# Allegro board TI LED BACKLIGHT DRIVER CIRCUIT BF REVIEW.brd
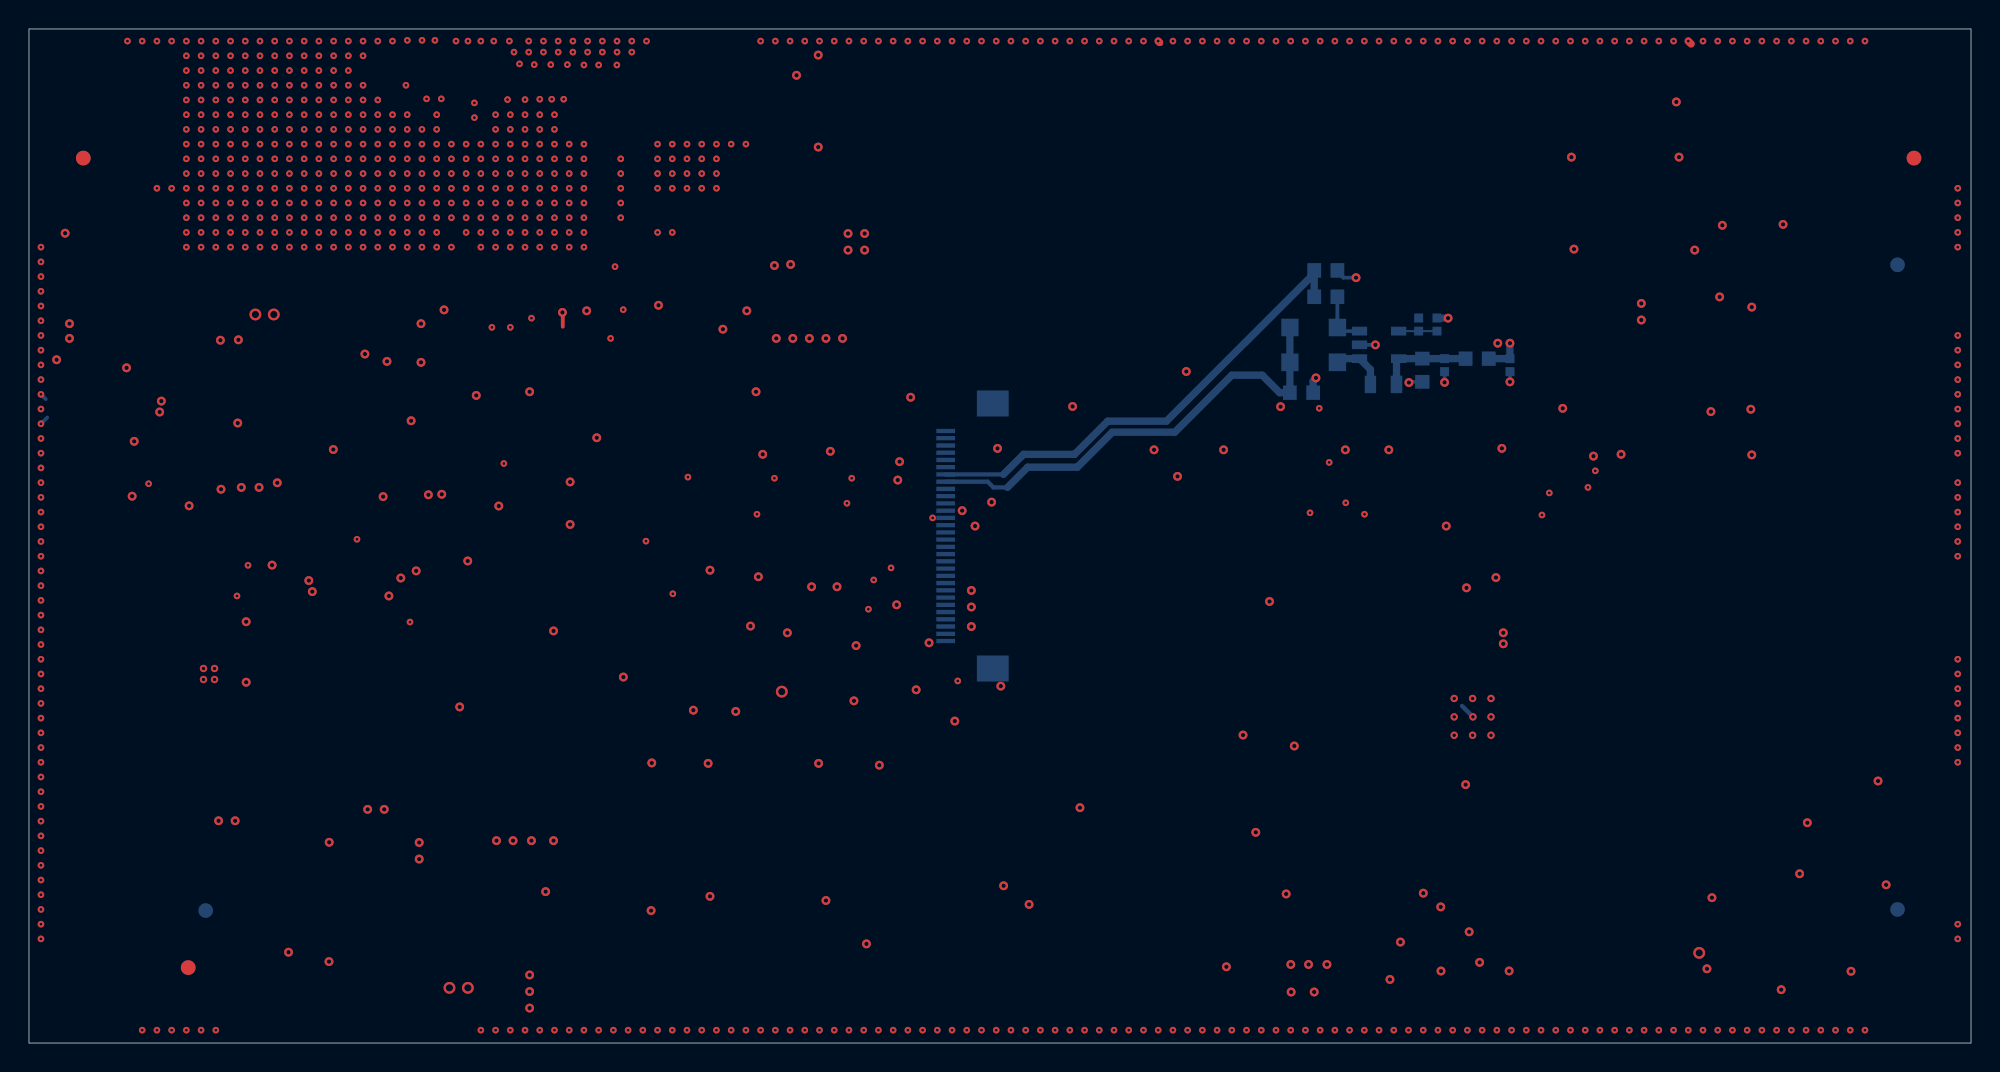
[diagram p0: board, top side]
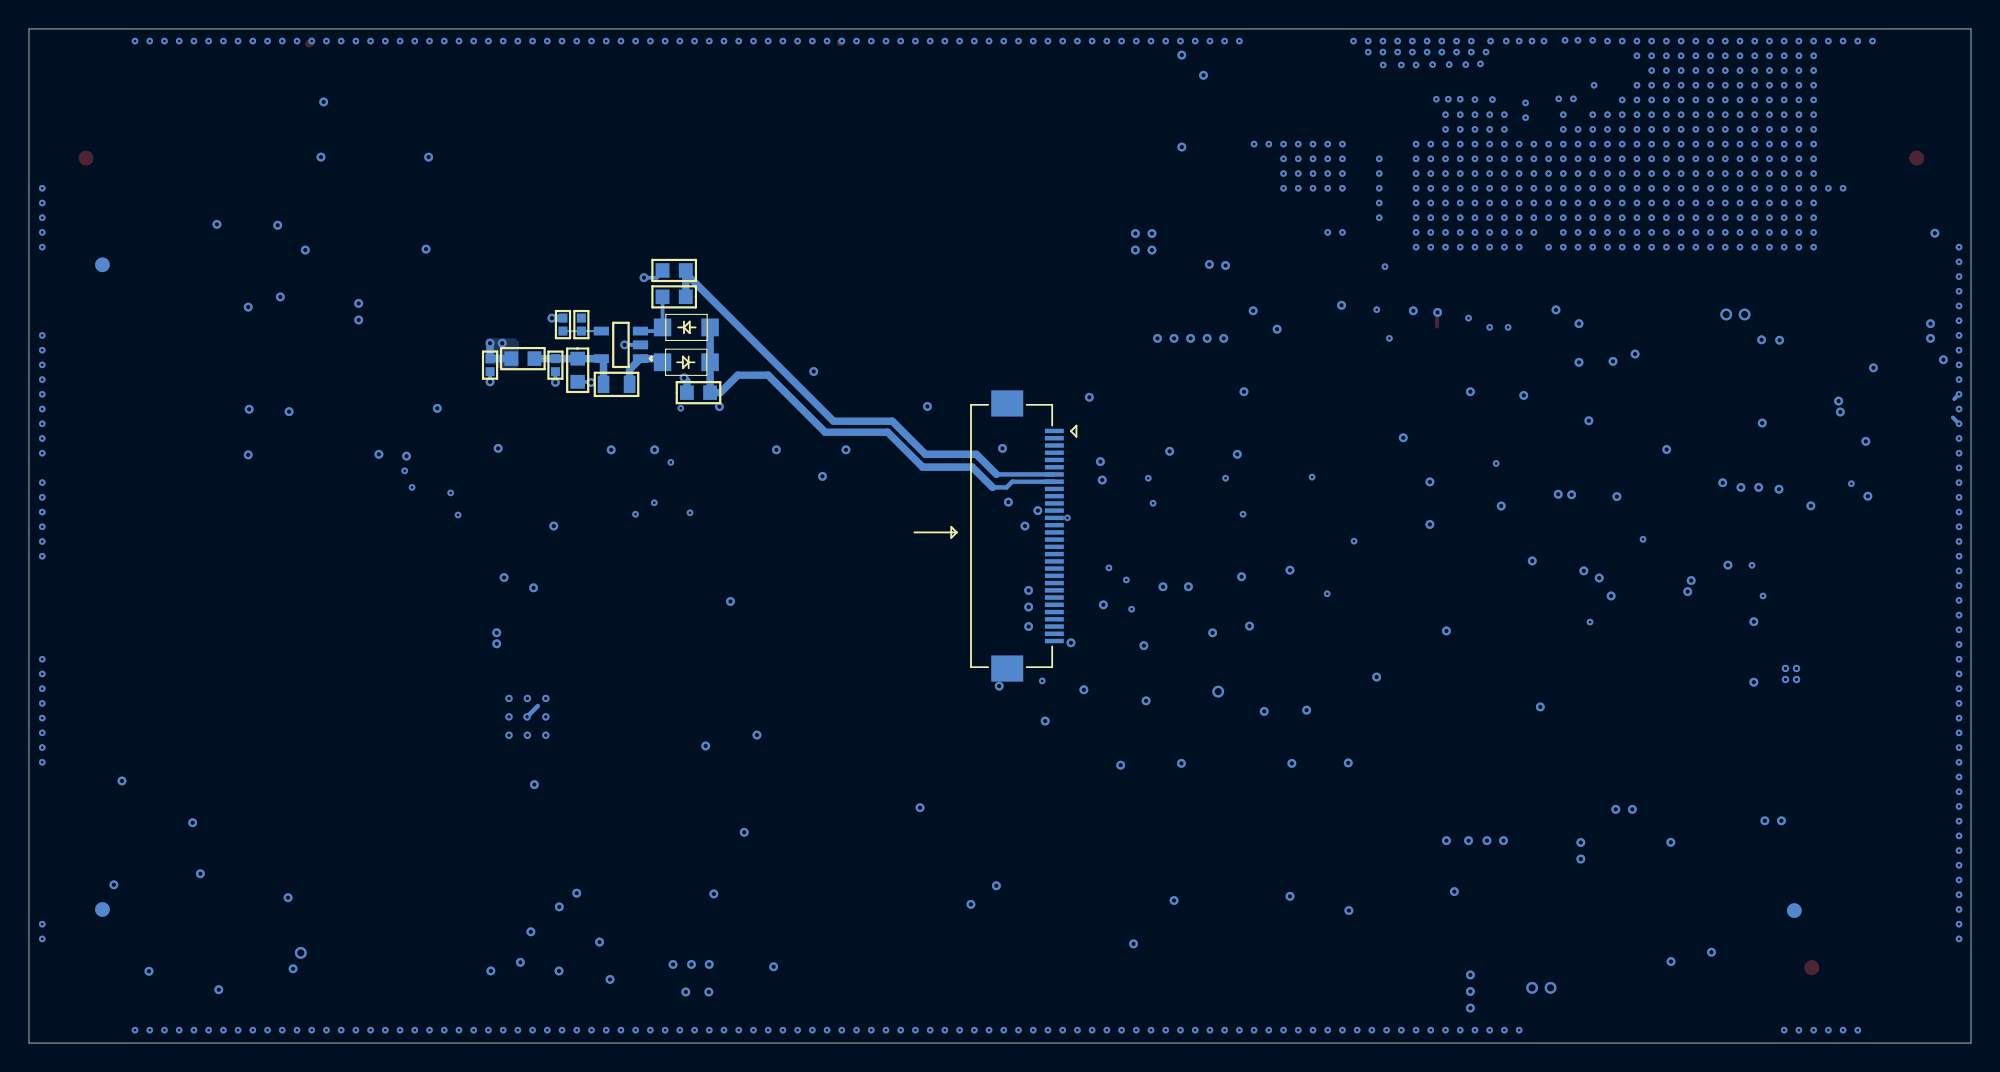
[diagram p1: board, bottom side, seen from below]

Outline 134 x 70 mm; copper layers: TOP, GND, SIG1, SIG2, VCC, BOTTOM. Coordinates in mm from the lower left corner of the outline.
Outline path: 0,70 0,0 134,0 134,70 0,70

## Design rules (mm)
net group DEFAULT: nets BACKLIGHT_DIM DIM_PWM1_OUT
net group POWER: nets GND LED_BACKLIGHT_A LED_BACKLIGHT_K N01711 N01793 VCC_3V3 VCC_5V_BCL VCC_5V_SW

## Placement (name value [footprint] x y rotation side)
C489  2.2uF,50V  [0603]  87.8 44.9 180 bottom
C490  10uF  [0603]  96.14 46.44 270 bottom
C491  0.1uF  [0402]  102.19 46.79 270 bottom
C749  0.1uF  [0402]  97.67 46.79 270 bottom
D51  PMEG4005EGWX  [SOD_123]  90.28 46.99 180 bottom
D52  DFLZ30-TP  [SOD_123]  87 49.4 0 bottom
FB66  74279228111  [0603]  99.92 47.24 0 bottom
J70  FH12S-30S-0-5SH_55  [HRS_FH12-30S-0_5SH]  63.25 42.25 270 bottom
L6  15uH  [IND_MLZ2012N]  94.36 45.47 180 bottom
NOREF  -  []  -123.96 2.55 90 top
NOREF#2  -  []  -32.31 7.14 90 top
NOREF#3  -  []  -30.16 5.64 90 top
NOREF#4  -  []  10.25 37.12 0 top
NOREF#5  -  []  -30.16 5.64 0 top
NOREF#6  -  []  10.6 41.2 0 top
NOREF#7  -  []  23.75 37.3 90 top
NOREF#8  -  []  4 0 90 top
NOREF#9  -  []  12.25 37.3 0 top
NOREF#10  -  []  -33.16 4.7 0 top
NOREF#11  -  []  -33.76 11.11 0 top
NOREF#12  -  []  -32.31 7.14 0 top
NOREF#13  -  []  -30.16 5.64 0 top
NOREF#14  -  []  -33.76 2.34 90 top
NOREF#15  -  []  -124.96 3.55 0 top
NOREF#16  -  []  17.75 37.3 0 top
NOREF#17  -  []  -124.71 3.47 0 top
NOREF#18  -  []  0 70 0 top
NOREF#19  -  []  -23.63 27.09 90 top
NOREF#20  -  []  -124.88 3.05 0 top
NOREF#21  -  []  -124.71 2.62 90 top
NOREF#22  -  []  -28.38 27.09 0 top
NOREF#23  -  []  -14.61 3.74 90 top
NOREF#24  -  []  299.21 -187.96 0 top
NOREF#25  -  []  -28.16 28.95 0 top
R611  0E  [0603]  89.48 51.51 0 bottom
R612  4.87E  [0603]  89.48 53.33 0 bottom
R613  0E  [0402]  95.88 49.59 90 bottom
R614  10K  [0402]  97.15 49.59 90 bottom
U27  LM3410XMF/NOPB  [SOT23X0_95X3_05X1_75X1_45-5]  91.81 47.24 90 bottom
UNK*  -  [unnamed#2]  3.75 61.09 0 top
UNK*#2  -  [unnamed#2]  10.99 5.21 0 top
UNK*#3  -  [unnamed#2]  130.07 61.09 0 top
UNK*#4  -  [unnamed#2]  12.19 9.14 180 bottom
UNK*#5  -  [unnamed#2]  128.93 9.22 180 bottom
UNK*#6  -  [unnamed#2]  128.93 53.72 180 bottom

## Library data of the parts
C489 = CAP NP
C490 C491 C749 = CAPACITOR NON-POL
D51 = DIODE SCHOTTKY
D52 = DIODE ZENER
FB66 = INDUCTOR FERRITE
J70 = FH12S-30S-0-5SH_3
L6 = INDUCTOR
R611-R614 = RES
U27 = LM3410XMF/NOPB

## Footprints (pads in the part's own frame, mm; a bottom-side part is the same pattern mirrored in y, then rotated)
0402
  rect 0.62x0.62 smd: 1(-0.45,0) 2(0.45,0)
0603
  rect 0.95x1 smd: 1(-0.8,0) 2(0.8,0)
HRS_FH12-30S-0_5SH
  rect 0.3x1.3 smd: 1(0,0) 2(0.5,0) 3(1,0) 4(1.5,0) 5(2,0) 6(2.5,0) 7(3,0) 8(3.5,0) 9(4,0) 10(4.5,0) 11(5,0) 12(5.5,0) 13(6,0) 14(6.5,0) 15(7,0) 16(7.5,0) 17(8,0) 18(8.5,0) 19(9,0) 20(9.5,0) 21(10,0) 22(10.5,0) 23(11,0) 24(11.5,0) 25(12,0) 26(12.5,0) 27(13,0) 28(13.5,0) 29(14,0) 30(14.5,0)
  rect 1.8x2.2 smd: MH1(16.4,-3.25) MH2(-1.9,-3.25)
IND_MLZ2012N
  rect 0.8x1.2 smd: 1(0,0) 2(1.8,0)
SOD_123
  rect 1.2x1.22 smd: 1(0,0) 2(3.28,0)
SOT23X0_95X3_05X1_75X1_45-5
  rect 0.6x1.05 smd: 1(0,0) 2(0.95,0) 3(1.9,0) 4(1.9,2.7) 5(0,2.7)
unnamed#2
  round 1.016 smd: (0,0)

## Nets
GND: C489.1 C490.2 C491.2 C749.2 R612.2 U27.2(GND)
GND1: J70.28(GND1)
GND2: J70.25(GND2)
GND4: J70.19(GND4)
GND5: J70.16(GND5)
GND6: J70.9(GND6)
VCC_3V3: R614.2
VCC_5V_BCL: C490.1 C749.1 FB66.1 L6.1 U27.5(VIN)
VCC_5V_SW: C491.1 FB66.2
BACKLIGHT_DIM: R613.1 R614.1 U27.4(DIM)
DIM_PWM1_OUT: R613.2
IOVCC: J70.15(IOVCC)
LED_BACKLIGHT_A: C489.2 D51.2(CATHODE) D52.1(CATHODE) J70.8(LEDA)
LED_BACKLIGHT_K: J70.7(LEDK) R611.1 R612.1
VCI: J70.10(VCI)
N01711: D51.1(ANODE) L6.2 U27.1(SW)
N01793: D52.2(ANODE) R611.2 U27.3(FB)

Pads without a net: J70 1 2 3 4 5 6 11 12 13 14 17 18 20 21 22 23 24 26 27 29 30 MH1 MH2

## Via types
v1: diameter 0.61, hole 0.305, TOP to BOTTOM, 188 vias
v2: diameter 0.813, hole 0.508, TOP to BOTTOM, 6 vias
v3: diameter 0.457, hole 0.203, TOP to BOTTOM, 700 vias
v4: diameter 0.508, hole 0.254, TOP to BOTTOM, 13 vias

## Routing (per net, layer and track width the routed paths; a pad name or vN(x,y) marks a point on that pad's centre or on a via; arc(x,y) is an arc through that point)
GND: length 10.1
  TOP w0.254: v1(36.81,50.43) 36.83,50.41 36.83,49.45 ; 78.11,68.97 78.01,69.07
  TOP w0.508: v3(114.49,69.16) 114.68,68.97 ; 78.01,69.07 v3(77.92,69.16)
  BOTTOM w0.144: 62.25,36.25 v3(62.35,36.25)
  BOTTOM w0.254: U27.2 v1(92.9,48.19) ; 1.16,44.45 v3(0.83,44.78) ; v1(91.57,52.83) 90.68,52.83 90.28,53.23 R612.2 ; 1.26,43.18 v3(0.83,42.75) ; C490.2 95.27,45.64 v1(95.21,45.59) ; C749.2 v1(97.67,45.6) ; v3(90.11,0.89) 90.1,0.89 ; 26.8,12.83 v1(26.92,12.7) ; C491.2 v1(102.19,45.64)
  BOTTOM w0.3: v4(99.63,22.52) 98.88,23.27
  BOTTOM w0.508: v1(88.8,45.92) 88.8,45.89 88.6,45.69 C489.1
  vias: v1(1.91,47.17) v1(2.49,55.9) v1(6.73,46.61) v1(7.12,37.75) v1(7.26,41.53) v1(9.02,43.56) v1(9.13,44.31) v1(11.05,37.08) v1(13.21,48.51) v1(13.25,38.23) v1(14.45,48.54) v1(14.4,42.8) v1(14.65,38.35) v1(14.99,29.08) v1(14.99,24.91) v1(15.88,38.35) v1(16.77,32.99) v1(17.13,38.68) v1(17.91,6.27) v1(19.31,31.92) v1(19.55,31.16) v1(20.71,13.86) v1(20.7,5.62) v1(21,40.97) v1(23.18,47.56) v1(23.37,16.13) v1(24.43,37.72) v1(24.51,16.13) v1(24.7,47.05) v1(24.83,30.86) v1(25.65,32.1) v1(26.37,42.96) v1(26.72,32.59) v1(26.92,13.84) v1(27.05,49.66) v1(27.05,46.99) v1(27.56,37.85) v1(28.48,37.88) v1(28.64,50.61) v1(29.72,23.2) v1(30.27,33.28) v1(30.86,44.7) v1(32.41,37.07) v1(34.54,44.96) v1(34.54,4.7) v1(34.54,3.56) v1(34.54,2.41) v1(35.65,10.45) v1(36.2,28.45) v1(37.34,38.73) v1(37.34,35.8) v1(38.48,50.55) v1(39.17,41.78) v1(41.01,25.26) v1(42.93,9.14) v1(42.97,19.34) v1(43.43,50.93) v1(45.84,22.98) v1(46.86,19.3) v1(46.99,32.64) v1(46.99,10.13) v1(47.88,49.28) v1(48.77,22.89) v1(49.53,50.55) v1(49.78,28.78) v1(50.16,44.96) v1(50.33,32.19) v1(50.63,40.64) v1(51.44,53.67) v1(51.56,48.64) v1(52.33,28.32) v1(52.55,53.75) v1(52.7,48.64) v1(52.96,66.8) v1(53.85,48.64) v1(54,31.5) v1(54.46,68.2) v1(54.46,61.85) v1(54.48,19.3) v1(54.99,48.64) v1(54.99,9.84) v1(55.29,40.85) v1(55.75,31.5) v1(56.13,48.64) v1(56.52,55.88) v1(56.52,54.74) v1(56.92,23.62) v1(57.07,27.43) v1(57.66,55.88) v1(57.66,54.74) v1(57.78,6.84) v1(58.67,19.18) v1(59.94,38.86) v1(59.87,30.25) v1(60.07,40.13) v1(61.21,24.38) v1(62.1,27.63) v1(63.88,22.23) v1(64.39,36.75) v1(65.03,31.24) v1(65.02,30.1) v1(65.02,28.75) v1(65.28,35.69) v1(66.42,37.34) v1(66.83,41.05) v1(67.06,24.64) v1(67.25,10.85) v1(69.01,9.57) v1(72.01,43.94) v1(72.52,16.25) v1(77.63,40.95) v1(79.25,39.12) v1(79.85,46.35) v1(82.43,40.95) v1(82.62,5.26) v1(83.77,21.26) v1(84.65,14.54) v1(85.6,30.48) v1(86.36,43.93) v1(86.75,10.29) v1(87.06,5.42) v1(87.09,3.52) v1(87.31,20.5) v1(88.29,5.42) v1(88.68,3.52) v1(89.56,5.42) v1(90.83,40.95) v1(93.83,40.95) v1(93.91,4.39) v1(94.63,6.97) v1(96.21,10.34) v1(97.41,9.4) v1(97.43,4.97) v1(97.79,35.69) v1(99.13,17.84) v1(99.19,31.42) v1(99.37,7.68) v1(100.09,5.57) v1(101.63,41.05) v1(101.73,28.32) v1(101.73,27.56) v1(102.13,4.97) v1(105.83,43.81) v1(106.43,61.15) v1(106.6,54.8) v1(107.95,40.51) v1(109.86,40.64) v1(113.67,64.96) v1(113.85,61.15) v1(114.94,54.74) v1(115.78,5.13) v1(116.05,43.59) v1(116.12,10.03) v1(116.66,51.5) v1(116.84,56.45) v1(118.81,43.75) v1(118.87,50.8) v1(118.87,40.6) v1(120.9,3.68) v1(121.03,56.51) v1(122.17,11.68) v1(122.71,15.21) v1(125.72,4.95) v1(127.58,18.09) v1(128.14,10.92) v2(15.62,50.29) v2(16.89,50.29) v2(51.94,24.26) v3(0.83,54.94) v3(0.83,53.92) v3(0.83,52.91) v3(0.83,51.89) v3(0.83,50.88) v3(0.83,49.86) v3(0.83,48.84) v3(0.83,47.83) v3(0.83,46.81) v3(0.83,45.8) v3(0.83,43.76) v3(0.83,41.73) v3(0.83,40.72) v3(0.83,39.7) v3(0.83,38.68) v3(0.83,37.67) v3(0.83,36.65) v3(0.83,35.64) v3(0.83,34.62) v3(0.83,33.6) v3(0.83,32.59) v3(0.83,31.57) v3(0.83,30.56) v3(0.83,29.54) v3(0.83,28.52) v3(0.83,27.51) v3(0.83,26.49) v3(0.83,25.48) v3(0.83,24.46) v3(0.83,23.44) v3(0.83,22.43) v3(0.83,21.41) v3(0.83,20.4) v3(0.83,19.38) v3(0.83,18.36) v3(0.83,17.35) v3(0.83,16.33) v3(0.83,15.32) v3(0.83,14.3) v3(0.83,13.28) v3(0.83,12.27) v3(0.83,11.25) v3(0.83,10.24) v3(0.83,9.22) v3(0.83,8.2) v3(0.83,7.19) v3(6.8,69.16) v3(7.81,69.16) v3(7.81,0.89) v3(8.26,38.61) v3(8.83,69.16) v3(8.83,59) v3(8.83,0.89) v3(9.84,69.16) v3(9.84,59) v3(9.84,0.89) v3(10.86,69.16) v3(10.86,68.15) v3(10.86,67.13) v3(10.86,66.12) v3(10.86,65.1) v3(10.86,64.08) v3(10.86,63.07) v3(10.86,62.05) v3(10.86,61.04) v3(10.86,60.02) v3(10.86,59) v3(10.86,57.99) v3(10.86,56.97) v3(10.86,55.96) v3(10.86,54.94) v3(10.86,0.89) v3(11.88,69.16) v3(11.88,68.15) v3(11.88,67.13) v3(11.88,66.12) v3(11.88,65.1) v3(11.88,64.08) v3(11.88,63.07) v3(11.88,62.05) v3(11.88,61.04) v3(11.88,60.02) v3(11.88,59) v3(11.88,57.99) v3(11.88,56.97) v3(11.88,55.96) v3(11.88,54.94) v3(11.88,0.89) v3(12.89,69.16) v3(12.89,68.15) v3(12.89,67.13) v3(12.89,66.12) v3(12.89,65.1) v3(12.89,64.08) v3(12.89,63.07) v3(12.89,62.05) v3(12.89,61.04) v3(12.89,60.02) v3(12.89,59) v3(12.89,57.99) v3(12.89,56.97) v3(12.89,55.96) v3(12.89,54.94) v3(12.89,0.89) v3(13.91,69.16) v3(13.91,68.15) v3(13.91,67.13) v3(13.91,66.12) v3(13.91,65.1) v3(13.91,64.08) v3(13.91,63.07) v3(13.91,62.05) v3(13.91,61.04) v3(13.91,60.02) v3(13.91,59) v3(13.91,57.99) v3(13.91,56.97) v3(13.91,55.96) v3(13.91,54.94) v3(14.35,30.86) v3(14.92,69.16) v3(14.92,68.15) v3(14.92,67.13) v3(14.92,66.12) v3(14.92,65.1) v3(14.92,64.08) v3(14.92,63.07) v3(14.92,62.05) v3(14.92,61.04) v3(14.92,60.02) v3(14.92,59) v3(14.92,57.99) v3(14.92,56.97) v3(14.92,55.96) v3(14.92,54.94) v3(15.11,32.98) v3(15.94,69.16) v3(15.94,68.15) v3(15.94,67.13) v3(15.94,66.12) v3(15.94,65.1) v3(15.94,64.08) v3(15.94,63.07) v3(15.94,62.05) v3(15.94,61.04) v3(15.94,60.02) v3(15.94,59) v3(15.94,57.99) v3(15.94,56.97) v3(15.94,55.96) v3(15.94,54.94) v3(16.96,69.16) v3(16.96,68.15) v3(16.96,67.13) v3(16.96,66.12) v3(16.96,65.1) v3(16.96,64.08) v3(16.96,63.07) v3(16.96,62.05) v3(16.96,61.04) v3(16.96,60.02) v3(16.96,59) v3(16.96,57.99) v3(16.96,56.97) v3(16.96,55.96) v3(16.96,54.94) v3(17.97,69.16) v3(17.97,68.15) v3(17.97,67.13) v3(17.97,66.12) v3(17.97,65.1) v3(17.97,64.08) v3(17.97,63.07) v3(17.97,62.05) v3(17.97,61.04) v3(17.97,60.02) v3(17.97,59) v3(17.97,57.99) v3(17.97,56.97) v3(17.97,55.96) v3(17.97,54.94) v3(18.99,69.16) v3(18.99,68.15) v3(18.99,67.13) v3(18.99,66.12) v3(18.99,65.1) v3(18.99,64.08) v3(18.99,63.07) v3(18.99,62.05) v3(18.99,61.04) v3(18.99,60.02) v3(18.99,59) v3(18.99,57.99) v3(18.99,56.97) v3(18.99,55.96) v3(18.99,54.94) v3(20,69.16) v3(20,68.15) v3(20,67.13) v3(20,66.12) v3(20,65.1) v3(20,64.08) v3(20,63.07) v3(20,62.05) v3(20,61.04) v3(20,60.02) v3(20,59) v3(20,57.99) v3(20,56.97) v3(20,55.96) v3(20,54.94) v3(21.02,69.16) v3(21.02,68.15) v3(21.02,67.13) v3(21.02,66.12) v3(21.02,65.1) v3(21.02,64.08) v3(21.02,63.07) v3(21.02,62.05) v3(21.02,61.04) v3(21.02,60.02) v3(21.02,59) v3(21.02,57.99) v3(21.02,56.97) v3(21.02,55.96) v3(21.02,54.94) v3(22.04,69.16) v3(22.04,68.15) v3(22.04,67.13) v3(22.04,66.12) v3(22.04,65.1) v3(22.04,64.08) v3(22.04,63.07) v3(22.04,62.05) v3(22.04,61.04) v3(22.04,60.02) v3(22.04,59) v3(22.04,57.99) v3(22.04,56.97) v3(22.04,55.96) v3(22.04,54.94) v3(22.63,34.77) v3(23.05,69.16) v3(23.05,68.15) v3(23.05,66.12) v3(23.05,65.1) v3(23.05,64.08) v3(23.05,63.07) v3(23.05,62.05) v3(23.05,61.04) v3(23.05,60.02) v3(23.05,59) v3(23.05,57.99) v3(23.05,56.97) v3(23.05,55.96) v3(23.05,54.94) v3(24.07,69.16) v3(24.07,65.1) v3(24.07,64.08) v3(24.07,63.07) v3(24.07,62.05) v3(24.07,61.04) v3(24.07,60.02) v3(24.07,59) v3(24.07,57.99) v3(24.07,56.97) v3(24.07,55.96) v3(24.07,54.94) v3(25.08,69.16) v3(25.08,64.08) v3(25.08,63.07) v3(25.08,62.05) v3(25.08,61.04) v3(25.08,60.02) v3(25.08,59) v3(25.08,57.99) v3(25.08,56.97) v3(25.08,55.96) v3(25.08,54.94) v3(26.01,66.12) v3(26.11,69.22) v3(26.1,64.08) v3(26.1,63.07) v3(26.1,62.05) v3(26.1,61.04) v3(26.1,60.02) v3(26.1,59) v3(26.1,57.99) v3(26.1,56.97) v3(26.1,55.96) v3(26.1,54.94) v3(26.29,29.06) v3(27.12,69.22) v3(27.12,63.07) v3(27.12,62.05) v3(27.12,61.04) v3(27.12,60.02) v3(27.12,59) v3(27.12,57.99) v3(27.12,56.97) v3(27.12,55.96) v3(27.12,54.94) v3(27.43,65.18) v3(28.01,69.22) v3(28.13,64.08) v3(28.13,63.07) v3(28.13,62.05) v3(28.13,61.04) v3(28.13,60.02) v3(28.13,59) v3(28.13,57.99) v3(28.13,56.97) v3(28.13,55.96) v3(28.13,54.94) v3(28.45,65.18) v3(29.15,62.05) v3(29.15,61.04) v3(29.15,60.02) v3(29.15,59) v3(29.15,57.99) v3(29.15,56.97) v3(29.15,54.94) v3(29.46,69.16) v3(30.16,62.05) v3(30.16,61.04) v3(30.16,60.02) v3(30.16,59) v3(30.16,57.99) v3(30.16,56.97) v3(30.16,55.96) v3(30.29,69.16) v3(30.73,64.9) v3(30.73,63.88) v3(31.18,69.16) v3(31.18,62.05) v3(31.18,61.04) v3(31.18,60.02) v3(31.18,59) v3(31.18,57.99) v3(31.18,56.97) v3(31.18,55.96) v3(31.18,54.94) v3(31.18,0.89) v3(31.94,49.4) v3(32.07,69.16) v3(32.2,64.08) v3(32.2,63.07) v3(32.2,62.05) v3(32.2,61.04) v3(32.2,60.02) v3(32.2,59) v3(32.2,57.99) v3(32.2,56.97) v3(32.2,55.96) v3(32.2,54.94) v3(32.2,0.89) v3(32.77,40.01) v3(33.02,65.13) v3(33.15,69.16) v3(33.21,64.08) v3(33.21,63.07) v3(33.21,62.05) v3(33.21,61.04) v3(33.21,60.02) v3(33.21,59) v3(33.21,57.99) v3(33.21,56.97) v3(33.21,55.96) v3(33.21,54.94) v3(33.21,49.4) v3(33.21,0.89) v3(33.47,68.4) v3(33.85,67.59) v3(34.23,65.13) v3(34.23,64.08) v3(34.23,63.07) v3(34.23,62.05) v3(34.23,61.04) v3(34.23,60.02) v3(34.23,59) v3(34.23,57.99) v3(34.23,56.97) v3(34.23,55.96) v3(34.23,54.94) v3(34.23,0.89) v3(34.48,69.16) v3(34.48,68.4) v3(34.67,50.04) v3(34.86,67.54) v3(35.24,65.15) v3(35.24,64.08) v3(35.24,63.07) v3(35.24,62.05) v3(35.24,61.04) v3(35.24,60.02) v3(35.24,59) v3(35.24,57.99) v3(35.24,56.97) v3(35.24,55.96) v3(35.24,54.94) v3(35.24,0.89) v3(35.5,69.16) v3(35.5,68.4) v3(36.01,67.54) v3(36.07,65.15) v3(36.26,64.08) v3(36.26,63.07) v3(36.26,62.05) v3(36.26,61.04) v3(36.26,60.02) v3(36.26,59) v3(36.26,57.99) v3(36.26,56.97) v3(36.26,55.96) v3(36.26,54.94) v3(36.26,0.89) v3(36.51,69.16) v3(36.51,68.4) v3(36.89,65.15) v3(37.15,67.54) v3(37.28,62.05) v3(37.28,61.04) v3(37.28,60.02) v3(37.28,59) v3(37.28,57.99) v3(37.28,56.97) v3(37.28,55.96) v3(37.28,54.94) v3(37.28,0.89) v3(37.53,69.16) v3(37.53,68.4) v3(38.29,67.51) v3(38.29,62.05) v3(38.29,61.04) v3(38.29,60.02) v3(38.29,59) v3(38.29,57.99) v3(38.29,56.97) v3(38.29,55.96) v3(38.29,54.94) v3(38.29,0.89) v3(38.55,69.16) v3(38.55,68.4) v3(39.31,67.51) v3(39.31,0.89) v3(39.56,69.16) v3(39.56,68.4) v3(40.13,48.64) v3(40.32,0.89) v3(40.44,53.59) v3(40.58,69.16) v3(40.58,68.4) v3(40.56,67.51) v3(40.83,61.04) v3(40.83,60.02) v3(40.83,59) v3(40.83,57.99) v3(40.83,56.97) v3(41,50.62) v3(41.34,0.89) v3(41.59,69.16) v3(41.59,68.4) v3(42.36,0.89) v3(42.61,69.16) v3(42.57,34.65) v3(43.37,62.05) v3(43.37,61.04) v3(43.37,60.02) v3(43.37,59) v3(43.37,55.96) v3(43.37,0.89) v3(44.39,62.05) v3(44.39,61.04) v3(44.39,60.02) v3(44.39,59) v3(44.39,55.96) v3(44.42,31.01) v3(44.39,0.89) v3(45.4,62.05) v3(45.4,61.04) v3(45.4,60.02) v3(45.4,59) v3(45.4,0.89) v3(45.47,39.07) v3(46.42,62.05) v3(46.42,61.04) v3(46.42,60.02) v3(46.42,59) v3(46.42,0.89) v3(47.44,62.05) v3(47.44,61.04) v3(47.44,60.02) v3(47.44,59) v3(47.44,0.89) v3(48.45,62.05) v3(48.45,0.89) v3(49.47,62.05) v3(49.47,0.89) v3(50.23,36.5) v3(50.48,69.16) v3(50.48,0.89) v3(51.44,38.99) v3(51.5,69.16) v3(51.5,0.89) v3(52.52,69.16) v3(52.52,0.89) v3(53.53,69.16) v3(53.53,0.89) v3(54.55,69.16) v3(54.55,0.89) v3(55.56,69.16) v3(55.56,0.89) v3(56.44,37.26) v3(56.58,69.16) v3(56.58,0.89) v3(56.77,38.99) v3(57.6,69.16) v3(57.6,0.89) v3(57.92,29.95) v3(58.29,31.97) v3(58.61,69.16) v3(58.61,0.89) v3(59.48,32.8) v3(59.63,69.16) v3(59.63,0.89) v3(60.64,69.16) v3(60.64,0.89) v3(61.66,69.16) v3(61.66,0.89) v3(62.68,69.16) v3(62.68,0.89) v3(63.69,69.16) v3(63.69,0.89) v3(64.08,24.99) v3(64.71,69.16) v3(64.71,0.89) v3(65.72,69.16) v3(65.72,0.89) v3(66.74,69.16) v3(66.74,0.89) v3(67.76,69.16) v3(67.76,0.89) v3(68.77,69.16) v3(68.77,0.89) v3(69.79,69.16) v3(69.79,0.89) v3(70.8,69.16) v3(70.8,0.89) v3(71.82,69.16) v3(71.82,0.89) v3(72.84,69.16) v3(72.84,0.89) v3(73.85,69.16) v3(73.85,0.89) v3(74.87,69.16) v3(74.87,0.89) v3(75.88,69.16) v3(75.88,0.89) v3(76.9,69.16) v3(76.9,0.89) v3(77.92,0.89) v3(78.93,69.16) v3(78.93,0.89) v3(79.95,69.16) v3(79.95,0.89) v3(80.96,69.16) v3(80.96,0.89) v3(81.98,69.16) v3(81.98,0.89) v3(83,69.16) v3(83,0.89) v3(84.01,69.16) v3(84.01,0.89) v3(85.03,69.16) v3(85.03,0.89) v3(86.04,69.16) v3(86.04,0.89) v3(87.06,69.16) v3(87.06,0.89) v3(88.08,69.16) v3(88.08,0.89) v3(88.39,36.6) v3(89.03,43.81) v3(89.09,69.16) v3(89.09,0.89) v3(89.71,40.08) v3(90.11,69.16) v3(90.86,37.29) v3(91.12,69.16) v3(91.12,0.89) v3(92.14,69.16) v3(92.14,0.89) v3(92.15,36.5) v3(93.16,69.16) v3(93.16,0.89) v3(94.17,69.16) v3(94.17,0.89) v3(95.19,69.16) v3(95.19,0.89) v3(96.2,69.16) v3(96.2,0.89) v3(97.22,69.16) v3(97.22,0.89) v3(98.24,69.16) v3(98.24,0.89) v3(99.25,69.16) v3(99.25,0.89) v3(100.27,69.16) v3(100.27,0.89) v3(101.28,69.16) v3(101.28,0.89) v3(102.3,69.16) v3(102.3,0.89) v3(103.32,69.16) v3(103.32,0.89) v3(104.33,69.16) v3(104.33,0.89) v3(104.39,36.45) v3(104.9,37.97) v3(105.35,69.16) v3(105.35,0.89) v3(106.36,69.16) v3(106.36,0.89) v3(107.38,69.16) v3(107.38,0.89) v3(107.57,38.35) v3(108.08,39.5) v3(108.4,69.16) v3(108.4,0.89) v3(109.41,69.16) v3(109.41,0.89) v3(110.43,69.16) v3(110.43,0.89) v3(111.44,69.16) v3(111.44,0.89) v3(112.46,69.16) v3(112.46,0.89) v3(113.48,69.16) v3(113.48,0.89) v3(114.49,0.89) v3(115.51,69.16) v3(115.51,0.89) v3(116.52,69.16) v3(116.52,0.89) v3(117.54,69.16) v3(117.54,0.89) v3(118.56,69.16) v3(118.56,0.89) v3(119.57,69.16) v3(119.57,0.89) v3(120.59,69.16) v3(120.59,0.89) v3(121.6,69.16) v3(121.6,0.89) v3(122.62,69.16) v3(122.62,0.89) v3(123.64,69.16) v3(123.64,0.89) v3(124.65,69.16) v3(124.65,0.89) v3(125.67,69.16) v3(125.67,0.89) v3(126.68,69.16) v3(126.68,0.89) v3(133.08,59) v3(133.08,57.99) v3(133.08,56.97) v3(133.08,55.96) v3(133.08,54.94) v3(133.08,48.84) v3(133.08,47.83) v3(133.08,46.81) v3(133.08,45.8) v3(133.08,44.78) v3(133.08,43.76) v3(133.08,42.75) v3(133.08,41.73) v3(133.08,40.72) v3(133.08,38.68) v3(133.08,37.67) v3(133.08,36.65) v3(133.08,35.64) v3(133.08,34.62) v3(133.08,33.6) v3(133.08,26.49) v3(133.08,25.48) v3(133.08,24.46) v3(133.08,23.44) v3(133.08,22.43) v3(133.08,21.41) v3(133.08,20.4) v3(133.08,19.38) v3(133.08,8.2) v3(133.08,7.19) v4(12.04,25.86) v4(12.04,25.09) v4(12.8,25.86) v4(12.8,25.09) v4(98.34,23.79) v4(98.34,22.52) v4(98.34,21.25) v4(99.61,23.79) v4(99.61,21.25) v4(100.88,23.79) v4(100.88,22.52) v4(100.88,21.25)
VCC_3V3: length 0.8
  BOTTOM w0.508: v1(97.92,50.04) 97.16,50.04 R614.2
  vias: v1(2.79,49.66) v1(2.79,48.64) v1(13.08,15.34) v1(14.22,15.34) v1(32.26,13.97) v1(33.4,13.97) v1(34.67,13.97) v1(36.2,13.97) v1(60.83,44.58) v1(101.22,32.13) v1(111.25,51.05) v1(111.25,49.91) v2(29.01,3.81) v2(30.28,3.81)
VCC_5V_BCL: length 6.5
  BOTTOM w0.508: FB66.1 C749.1 C490.1 U27.5 94.36,47.09 L6.1
VCC_5V_SW: length 2.5
  BOTTOM w0.508: v1(102.19,48.31) C491.1 FB66.2
  vias: v1(101.35,48.31) v2(115.24,6.22)
BACKLIGHT_DIM: length 2.6
  BOTTOM w0.144: R614.1 R613.1 U27.4
LED_BACKLIGHT_A: length 32.1
  BOTTOM w0.3: J70.8 66.15,38.75 66.55,38.35 67.51,38.35
  BOTTOM w0.508: D52.1 D51.2 C489.2 86.3,44.9 85.09,46.1 83,46.1 79.06,42.16 74.75,42.16 72.33,39.75 68.91,39.75 67.51,38.35
LED_BACKLIGHT_K: length 33
  BOTTOM w0.3: 67.24,39.25 J70.7
  BOTTOM w0.508: 67.24,39.25 68.63,40.64 72.14,40.64 74.43,42.93 78.49,42.93 88.68,53.12 ; 88.68,53.12 R612.1 ; 88.68,53.12 R611.1
N01711: length 3.7
  BOTTOM w0.508: L6.2 92.56,46.49 U27.1 90.54,47.24 D51.1
N01793: length 3.7
  BOTTOM w0.254: U27.3 90.54,49.14 D52.2 R611.2

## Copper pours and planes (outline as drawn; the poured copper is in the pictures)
GND on GND: 0.51,0.51 0.51,69.49 133.49,69.49 133.49,0.51 ; 5 cut-outs
GND on GND: 133.35,6.73 132.97,6.73 132.72,6.99 132.72,67.44 131.32,68.83 46.1,68.83 45.59,69.34 45.59,69.49 132.69,69.49 133.49,68.69 133.49,6.87 ; 1 cut-out
GND on SIG2: 1.14,55.24 1.27,55.12 1.27,5.33 5.33,1.27 126.87,1.27 127,1.14 127,0.76 126.75,0.51 1.4,0.51 0.64,1.27 0.64,5.84 0.51,5.97 0.51,55.12 0.64,55.24 ; 1 cut-out
GND on SIG2: 133.35,6.73 132.97,6.73 132.72,6.99 132.72,67.44 131.32,68.83 39.24,68.83 38.99,69.09 38.99,69.22 39.27,69.49 132.69,69.49 133.49,68.69 133.49,6.87 ; 2 cut-outs
GND on VCC: 1.14,55.24 1.27,55.12 1.27,5.33 5.33,1.27 126.87,1.27 127,1.14 127,0.76 126.75,0.51 1.4,0.51 0.64,1.27 0.64,6.22 0.51,6.35 0.51,55.12 0.64,55.24 ; 1 cut-out
VCC_3V3 on VCC: 0.51,7.87 0.51,56.9 35.56,56.9 45.21,47.24 45.21,36.83 48.39,33.66 56.52,33.66 58.67,35.81 58.67,44.45 59.18,44.96 60.96,44.96 62.87,43.05 64.64,43.05 65.66,44.07 65.66,46.48 66.04,46.86 69.85,46.86 70.1,46.61 70.1,44.96 70.87,44.2 77.6,44.2 80.01,46.61 80.01,52.58 78.49,54.1 78.49,58.8 73.53,63.75 68.07,63.75 67.69,64.14 67.69,68.33 67.82,68.45 128.78,68.45 132.21,65.02 132.21,3.56 130.43,1.78 6.86,1.78 0.76,7.87 ; 2 cut-outs
VCC_5V_SW on BOTTOM: 100.2,48.39 100.2,46.74 100.33,46.61 102.36,46.61 102.49,46.74 102.49,48.51 102.36,48.64 100.46,48.64

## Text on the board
BOTTOM: L6-BOTTOM
Ref Des/Assembly Bottom: ASSEMBLY BOTTOM
Package Geometry/Pastemask Bottom: PASTEMASK BOTTOM
Ref Des/Silkscreen Bottom: SILKSCREEN BOTTOM
User.Comments: THIS DOCUMENT CONTAINS INFORMATION | PROPRIETARY TO iWAVE SYSTEMS AND SHALL | NOT BE USED FOR ENGINEERING DESIGN | PROCUREMENT OR MANUFACTURE IN WHOLE | OR IN PART WITHOUT THE CONSENT OF | iWAVE SYSTEMS. | DRAWN | CHECKED | APPROVED | APPROVALS | DATE | TOLERANCES ARE: | ALL DIMENSIONS ARE IN: | MILLIMETERS | DECIMALS | INCHES | ____ | ANGLES | 1.0 | x.x | DRAWING TITLE | SCALE | SIZE | 1/1 | DO NOT SCALE DRAWING | iWave Systems technolgies Pvt. Ltd. | 7/B 29th Main BTM Layout, 2nd Stage, | Bangalore-560076, India | Web:www.iwavesystems.com | SHEET | 1  OF | DD-MM-YYYY | 1 | UNLESS OTHERWISE SPECIFIED | REV | ORIGINAL RELEASE | DESCRIPTION | REVISIONS | PRINTED CIRCUIT BOARD | D | SOLDERMASK BOTTOM | SOLDERMASK TOP
TOP: L1-TOP
Ref Des/Assembly Top: ASSEMBLY TOP
Package Geometry/Pastemask Top: PASTEMASK TOP
Ref Des/Silkscreen Top: SILKSCREEN TOP
SIG1: L3-SIG1
SIG2: L4-SIG2
PAGE_OUTLINE: FAB DETAILS | D | C | B | A | 8 | 7 | 6 | 5 | 4 | 3 | 2 | 1
User.8: L2-GND
User.9: L4-VCC
User.10: L9-VCC2
User.11: L7-GND2
User.14: L6-SIG6
User.15: L8-SIG4
User.16: FILM:
User.18: XXXXX | DD-MM-YYYY | P/N: | iW-XXXXX-BF-XX-RX.X-RELX.XX | XXXXXXXXXXXXXX | X
User.19: PREPREG | LAYER STACK UP | LAYER1-TOP | LAYER2-XXX | LAYER3-XXX | LAYER4-XXX | LAYER5-XXX | LAYER6-XXX | LAYER7-XXX | LAYER8-XXX | LAYER9-XXX | TOP SILKSCREEN | TOP SOLDERMASK | LAYER10-BOTTOM | BOTTOM SOLDERMASK | BOTTOM SILKSCREEN
User.21: CORE
User.25: 15.Fab Vendor is not to alter the supplied film or database without getting permission from iWave Systems technologies. | 16.Board impedance details are as shown below. For more information refer XXlayer_XXX.pdf provided with the gerber data | 10.Suppress unused pads for plated-through holes on internal conductor layers. | 11.Add Tear drop to all signal layers | 14.Electrical Test: All boards should be 100% electrically  tested for opens & shorts | 13.Finish boards shall not have nicks, scratches, voids, exposed copper,poor plating and mis-drilled holes | 12.The PWB will be marked as lead free process compatible by use of an Ink stamp | 17.Impedance control is required  for the board | 3.Solder mask (SMOBC)- Apply LPI Solder mask on both sides per IPC-SM-840,type B,class 3,color green | 4.Silkscreen- White Epoxy ink,both sides .No silk on pads | 5.Board thickness shall be _______ mm and tolerance +/- _____ | 6.Minimum Trace width and clearances are ___/___mils | 7.DRC's must be run on the Gerber before building boards | 1.PCB  fabrication shall meet the requirements of  IPC-A-600, class 2 (latest version ) | 2.Surface finish shall be - ENIG | 8.RS274X GERBER/ODB++ used for the fab must be verified against the IPC356A netlist | 9.This Fabrication process should be RoHS Complaint | LAYERS | IMPEDANCE | (Ohms) | SINGLE ENDED | TRACE | (MILS) | WIDTH | DIFFERENTIAL | SPACING
